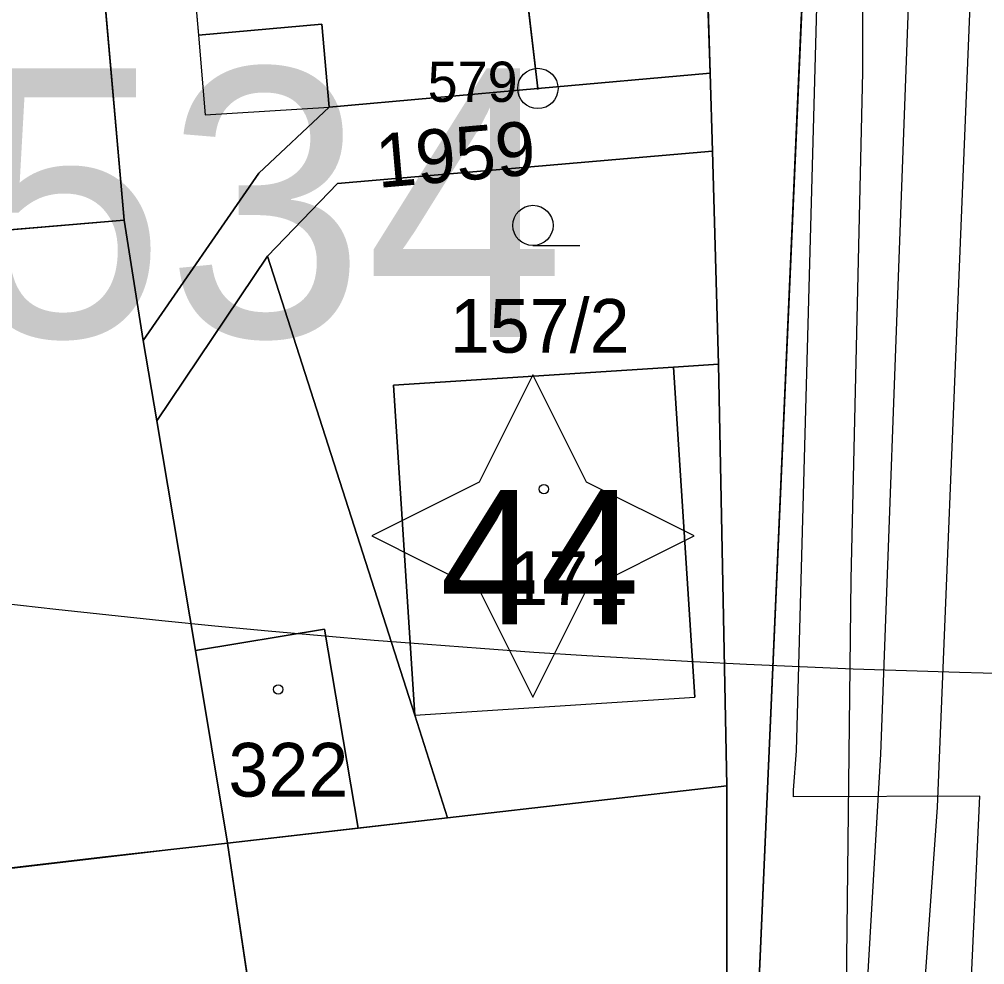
# Model space of a CAD drawing. Extents: x -706130 to -698555, y -971544 to -967260.
# Drawn here: x -704407.88 to -704371.94, y -970357.67 to -970322.46 of the extents above; entities that cross this region are included whole.
import ezdxf

# ---------------------------------------------------------------- set-up
doc = ezdxf.new("R2010")
doc.units = 0
for name, color, linetype in [('_Doplněk budov pro zastavěnost', 7, 'Continuous'), ('Architektonicky cenná stavba S', 7, 'Continuous'), ('BPEJ I-II trida ochrany S', 7, 'Continuous'), ('Docházková izochrona - BUS S', 7, 'Continuous'), ('Docházková izochrona - VLAK N', 7, 'Continuous'), ('Hranice intravilán', 7, 'Continuous'), ('Kanalizace_stoka bez rozlišení N', 7, 'Continuous'), ('KN_Budovy', 7, 'Continuous'), ('KN_Budovy_cisla_domovni', 7, 'Continuous'), ('KN_Hranice_parcel', 7, 'Continuous'), ('KN_Hranice_parcel_vnitrni_kresba', 7, 'Continuous'), ('KN_Parcelni cisla', 7, 'Continuous'), ('KN_Polygon parcely', 7, 'Continuous'), ('KN_POZEMKY_13_ZASTAVENA PLOCHA', 7, 'Continuous'), ('KN_POZEMKY_14_OSTATNI PLOCHA', 7, 'Continuous'), ('KN_POZEMKY_5_ZAHRADA', 7, 'Continuous'), ('KN_POZEMKY_7_TTP', 7, 'Continuous'), ('KN_VYUZITI_16_ostatni plocha_silnice', 7, 'Continuous'), ('KN_VYUZITI_17_ostatni plocha_ostatni komunikace', 7, 'Continuous'), ('KN_VYUZITI_20_ostatni plocha_sportoviste', 7, 'Continuous'), ('KN_Značky bodu BP', 7, 'Continuous'), ('KN_Značky budov', 7, 'Continuous'), ('KN_Značky kultur', 7, 'Continuous'), ('Komunikace III třídy osy S', 7, 'Continuous'), ('Nemovité kulturní památky popis', 7, 'Continuous'), ('Nemovité kulturní památky S', 7, 'Continuous'), ('Plochy doprava silniční - silnice III třídy S', 7, 'Continuous'), ('Plochy smíšené obytné venkovské S', 7, 'Continuous'), ('Plynovody STL S', 7, 'Continuous'), ('Regulační bloky zastavěné S', 7, 'Continuous'), ('Vodovodní řady - rozváděcí S', 7, 'Continuous')]:
    doc.layers.add(name, color=color, linetype=linetype)

msp = doc.modelspace()

# ---------------------------------------------------------------- linework, layer by layer
at = {"layer": '_Doplněk budov pro zastavěnost'}
for points in [[(-704396.34, -970325.73), (-704396.61, -970322.64), (-704401.2, -970323.05)], [(-704401.2, -970323.05), (-704400.954, -970326.017), (-704396.34, -970325.73)]]:
    msp.add_lwpolyline(points, dxfattribs=at)
at = {"layer": 'Architektonicky cenná stavba S'}
msp.add_lwpolyline([(-704388.754, -970335.704), (-704390.754, -970339.704), (-704394.754, -970341.704), (-704390.754, -970343.704), (-704388.754, -970347.704), (-704386.754, -970343.704), (-704382.754, -970341.704), (-704386.754, -970339.704)], close=True, dxfattribs=at)
at = {"layer": 'BPEJ I-II trida ochrany S'}
for p, q in [((-704403.97, -970329.94), (-704406.06, -970306.24)), ((-704382.07, -970327.37), (-704396.03, -970328.58)), ((-704381.84, -970335.31), (-704382.07, -970327.37)), ((-704396.03, -970328.58), (-704398.63, -970331.28)), ((-704403.26, -970334.42), (-704403.97, -970329.94)), ((-704398.63, -970331.28), (-704393.15, -970348.38)), ((-704402.76, -970337.42), (-704403.26, -970334.42)), ((-704383.52, -970335.42), (-704381.84, -970335.31)), ((-704393.94, -970336.09), (-704383.52, -970335.42)), ((-704393.15, -970348.38), (-704393.94, -970336.09)), ((-704401.32, -970345.97), (-704402.76, -970337.42)), ((-704400.12, -970353.14), (-704401.32, -970345.97)), ((-704395.76, -970382.45), (-704400.12, -970353.14))]:
    msp.add_line(p, q, dxfattribs=at)
at = {"layer": 'Docházková izochrona - BUS S'}
msp.add_arc((-704361.829, -969946.93), 400, 155.51821, 17.33949, dxfattribs=at)
at = {"layer": 'Docházková izochrona - VLAK N'}
msp.add_circle((-704165.451, -969778.767), 800, dxfattribs=at)
at = {"layer": 'Hranice intravilán'}
msp.add_lwpolyline([(-704381.54, -970369.54), (-704381.53, -970351.01), (-704391.93, -970352.2), (-704400.12, -970353.14), (-704436.16, -970357.37), (-704435.41, -970332.61), (-704434.49, -970307.92), (-704433.21, -970284.34), (-704432.24, -970260.61)], dxfattribs=at)
at = {"layer": 'Kanalizace_stoka bez rozlišení N'}
msp.add_lwpolyline([(-704315.708, -970108.899), (-704316.113, -970109.917), (-704324.867, -970134.026), (-704326.632, -970179.784), (-704337.75, -970213.085), (-704365.425, -970272.107), (-704371.374, -970294.506), (-704373.709, -970351.804), (-704376.113, -970385.719), (-704398.194, -970423.758)], dxfattribs=at)
at = {"layer": 'KN_Budovy'}
for points in [[(-704397.27, -970315.27), (-704401.85, -970315.68), (-704401.2, -970323.05), (-704396.61, -970322.64), (-704396.34, -970325.73), (-704388.57, -970325.04), (-704390.2, -970311.28), (-704397.56, -970312.03)], [(-704393.94, -970336.09), (-704393.15, -970348.38), (-704382.73, -970347.71), (-704383.52, -970335.42)], [(-704401.32, -970345.97), (-704400.12, -970353.14), (-704395.26, -970352.58), (-704396.51, -970345.18)]]:
    msp.add_lwpolyline(points, close=True, dxfattribs=at)
at = {"layer": 'KN_Hranice_parcel'}
for p, q in [((-704406.06, -970306.24), (-704403.97, -970329.94)), ((-704382.15, -970324.47), (-704382.57, -970312.21)), ((-704382.15, -970324.47), (-704382.07, -970327.37)), ((-704381.84, -970335.31), (-704382.07, -970327.37)), ((-704403.97, -970329.94), (-704435.41, -970332.61)), ((-704403.97, -970329.94), (-704403.26, -970334.42)), ((-704398.63, -970331.28), (-704402.76, -970337.42)), ((-704393.15, -970348.38), (-704398.63, -970331.28)), ((-704402.76, -970337.42), (-704403.26, -970334.42)), ((-704381.53, -970351.01), (-704381.84, -970335.31)), ((-704393.15, -970348.38), (-704391.93, -970352.2)), ((-704391.93, -970352.2), (-704381.53, -970351.01)), ((-704404.67, -970353.65), (-704400.12, -970353.14)), ((-704400.12, -970353.14), (-704395.76, -970382.45))]:
    msp.add_line(p, q, dxfattribs=at)
for points in [[(-704381.19, -970377.72), (-704380.01, -970350.84), (-704377.78, -970300.1), (-704377.45, -970297.32)], [(-704403.26, -970334.42), (-704398.96, -970328.19), (-704396.34, -970325.73), (-704388.57, -970325.04), (-704382.15, -970324.47)], [(-704382.07, -970327.37), (-704396.03, -970328.58), (-704398.63, -970331.28)], [(-704435.41, -970332.61), (-704436.16, -970357.37), (-704404.67, -970353.65)], [(-704381.84, -970335.31), (-704383.52, -970335.42), (-704393.94, -970336.09), (-704393.15, -970348.38)], [(-704402.76, -970337.42), (-704401.32, -970345.97), (-704400.12, -970353.14)], [(-704388.96, -970375.85), (-704387.88, -970369.26), (-704381.54, -970369.54), (-704381.53, -970351.01)], [(-704400.12, -970353.14), (-704395.26, -970352.58), (-704391.93, -970352.2)]]:
    msp.add_lwpolyline(points, dxfattribs=at)
at = {"layer": 'KN_Hranice_parcel_vnitrni_kresba'}
for p, q in [((-704390.2, -970311.28), (-704388.57, -970325.04)), ((-704401.85, -970315.68), (-704401.2, -970323.05)), ((-704401.2, -970323.05), (-704396.61, -970322.64)), ((-704396.61, -970322.64), (-704396.34, -970325.73)), ((-704383.52, -970335.42), (-704382.73, -970347.71)), ((-704401.32, -970345.97), (-704396.51, -970345.18)), ((-704396.51, -970345.18), (-704395.26, -970352.58)), ((-704393.15, -970348.38), (-704382.73, -970347.71))]:
    msp.add_line(p, q, dxfattribs=at)
at = {"layer": 'KN_Polygon parcely'}
msp.add_lwpolyline([(-704375.62, -970282.06), (-704376.41, -970288.62), (-704377.45, -970297.32), (-704377.78, -970300.1), (-704380.01, -970350.84), (-704381.19, -970377.72), (-704372.65, -970386.41), (-704371.76, -970369.3), (-704370.91, -970352.79), (-704370.59, -970346.53), (-704370.18, -970335.17), (-704369.52, -970316.88), (-704369.23, -970310.61), (-704368.75, -970300.09), (-704366.65, -970284.79), (-704361.08, -970269.38)], dxfattribs=at)
for points in [[(-704426.17, -970394.89), (-704421.76, -970392.36), (-704422.73, -970390.66), (-704416.04, -970386.82), (-704417.98, -970383.43), (-704409.73, -970378.7), (-704407.78, -970382.09), (-704403.26, -970379.5), (-704395.76, -970382.45), (-704400.12, -970353.14), (-704404.67, -970353.65), (-704436.16, -970357.37), (-704435.41, -970332.61), (-704434.49, -970307.92), (-704433.21, -970284.34), (-704437.36, -970284.18), (-704440.6, -970365.1), (-704426.93, -970393.32)], [(-704381.19, -970377.72), (-704380.01, -970350.84), (-704377.78, -970300.1), (-704377.45, -970297.32), (-704381.06, -970296.88), (-704381.15, -970298.64), (-704382.31, -970309.38), (-704382.57, -970312.21), (-704382.15, -970324.47), (-704382.07, -970327.37), (-704381.84, -970335.31), (-704381.53, -970351.01), (-704381.54, -970369.54), (-704387.88, -970369.26), (-704388.96, -970375.85)], [(-704406.09, -970304.49), (-704406.06, -970306.24), (-704403.97, -970329.94), (-704403.26, -970334.42), (-704398.96, -970328.19), (-704396.34, -970325.73), (-704388.57, -970325.04), (-704382.15, -970324.47), (-704382.57, -970312.21), (-704388.56, -970311.1), (-704389.75, -970308.75), (-704391.17, -970307.32), (-704394.63, -970305.83)], [(-704406.06, -970306.24), (-704434.49, -970307.92), (-704435.41, -970332.61), (-704403.97, -970329.94)], [(-704403.26, -970334.42), (-704402.76, -970337.42), (-704398.63, -970331.28), (-704396.03, -970328.58), (-704382.07, -970327.37), (-704382.15, -970324.47), (-704388.57, -970325.04), (-704396.34, -970325.73), (-704398.96, -970328.19)], [(-704381.84, -970335.31), (-704382.07, -970327.37), (-704396.03, -970328.58), (-704398.63, -970331.28), (-704393.15, -970348.38), (-704393.94, -970336.09), (-704383.52, -970335.42)], [(-704403.97, -970329.94), (-704435.41, -970332.61), (-704436.16, -970357.37), (-704404.67, -970353.65), (-704400.12, -970353.14), (-704401.32, -970345.97), (-704402.76, -970337.42), (-704403.26, -970334.42)], [(-704400.12, -970353.14), (-704395.26, -970352.58), (-704391.93, -970352.2), (-704393.15, -970348.38), (-704398.63, -970331.28), (-704402.76, -970337.42), (-704401.32, -970345.97)], [(-704393.94, -970336.09), (-704393.15, -970348.38), (-704391.93, -970352.2), (-704381.53, -970351.01), (-704381.84, -970335.31), (-704383.52, -970335.42)], [(-704387.88, -970369.26), (-704381.54, -970369.54), (-704381.53, -970351.01), (-704391.93, -970352.2), (-704395.26, -970352.58), (-704400.12, -970353.14), (-704395.76, -970382.45), (-704394.76, -970382.69), (-704392.9, -970374.9), (-704388.96, -970375.85)]]:
    msp.add_lwpolyline(points, close=True, dxfattribs=at)
at = {"layer": 'KN_POZEMKY_13_ZASTAVENA PLOCHA'}
for p, q in [((-704403.97, -970329.94), (-704406.06, -970306.24)), ((-704382.57, -970312.21), (-704382.15, -970324.47)), ((-704382.15, -970324.47), (-704388.57, -970325.04)), ((-704388.57, -970325.04), (-704396.34, -970325.73)), ((-704396.34, -970325.73), (-704398.96, -970328.19)), ((-704398.96, -970328.19), (-704403.26, -970334.42)), ((-704403.26, -970334.42), (-704403.97, -970329.94)), ((-704402.76, -970337.42), (-704398.63, -970331.28)), ((-704398.63, -970331.28), (-704393.15, -970348.38)), ((-704383.52, -970335.42), (-704381.84, -970335.31)), ((-704381.84, -970335.31), (-704381.53, -970351.01)), ((-704393.94, -970336.09), (-704383.52, -970335.42)), ((-704393.15, -970348.38), (-704393.94, -970336.09)), ((-704401.32, -970345.97), (-704402.76, -970337.42)), ((-704400.12, -970353.14), (-704401.32, -970345.97)), ((-704393.15, -970348.38), (-704391.93, -970352.2)), ((-704391.93, -970352.2), (-704393.15, -970348.38)), ((-704381.53, -970351.01), (-704391.93, -970352.2)), ((-704391.93, -970352.2), (-704395.26, -970352.58)), ((-704395.26, -970352.58), (-704400.12, -970353.14))]:
    msp.add_line(p, q, dxfattribs=at)
at = {"layer": 'KN_POZEMKY_14_OSTATNI PLOCHA'}
for p, q in [((-704380.01, -970350.84), (-704377.78, -970300.1)), ((-704377.78, -970300.1), (-704380.01, -970350.84)), ((-704382.15, -970324.47), (-704382.57, -970312.21)), ((-704388.57, -970325.04), (-704382.15, -970324.47)), ((-704382.15, -970324.47), (-704382.07, -970327.37)), ((-704382.07, -970327.37), (-704382.15, -970324.47)), ((-704396.34, -970325.73), (-704388.57, -970325.04)), ((-704398.96, -970328.19), (-704396.34, -970325.73)), ((-704382.07, -970327.37), (-704396.03, -970328.58)), ((-704381.84, -970335.31), (-704382.07, -970327.37)), ((-704403.26, -970334.42), (-704398.96, -970328.19)), ((-704396.03, -970328.58), (-704398.63, -970331.28)), ((-704398.63, -970331.28), (-704402.76, -970337.42)), ((-704402.76, -970337.42), (-704403.26, -970334.42)), ((-704381.53, -970351.01), (-704381.84, -970335.31)), ((-704391.93, -970352.2), (-704381.53, -970351.01)), ((-704381.53, -970351.01), (-704381.54, -970369.54)), ((-704381.54, -970369.54), (-704381.53, -970351.01)), ((-704381.19, -970377.72), (-704380.01, -970350.84)), ((-704380.01, -970350.84), (-704381.19, -970377.72)), ((-704395.26, -970352.58), (-704391.93, -970352.2)), ((-704400.12, -970353.14), (-704395.26, -970352.58)), ((-704395.76, -970382.45), (-704400.12, -970353.14))]:
    msp.add_line(p, q, dxfattribs=at)
at = {"layer": 'KN_POZEMKY_5_ZAHRADA'}
for p, q in [((-704406.06, -970306.24), (-704403.97, -970329.94)), ((-704396.03, -970328.58), (-704382.07, -970327.37)), ((-704382.07, -970327.37), (-704381.84, -970335.31)), ((-704398.63, -970331.28), (-704396.03, -970328.58)), ((-704403.97, -970329.94), (-704435.41, -970332.61)), ((-704393.15, -970348.38), (-704398.63, -970331.28)), ((-704381.84, -970335.31), (-704383.52, -970335.42)), ((-704383.52, -970335.42), (-704393.94, -970336.09)), ((-704393.94, -970336.09), (-704393.15, -970348.38))]:
    msp.add_line(p, q, dxfattribs=at)
at = {"layer": 'KN_POZEMKY_7_TTP'}
for p, q in [((-704435.41, -970332.61), (-704403.97, -970329.94)), ((-704403.97, -970329.94), (-704403.26, -970334.42)), ((-704403.26, -970334.42), (-704402.76, -970337.42)), ((-704402.76, -970337.42), (-704401.32, -970345.97)), ((-704401.32, -970345.97), (-704400.12, -970353.14)), ((-704404.67, -970353.65), (-704400.12, -970353.14)), ((-704400.12, -970353.14), (-704404.67, -970353.65)), ((-704400.12, -970353.14), (-704395.76, -970382.45)), ((-704436.16, -970357.37), (-704404.67, -970353.65)), ((-704404.67, -970353.65), (-704436.16, -970357.37))]:
    msp.add_line(p, q, dxfattribs=at)
at = {"layer": 'KN_VYUZITI_16_ostatni plocha_silnice'}
for p, q in [((-704380.01, -970350.84), (-704377.78, -970300.1)), ((-704381.19, -970377.72), (-704380.01, -970350.84))]:
    msp.add_line(p, q, dxfattribs=at)
at = {"layer": 'KN_VYUZITI_17_ostatni plocha_ostatni komunikace'}
for p, q in [((-704377.78, -970300.1), (-704380.01, -970350.84)), ((-704382.15, -970324.47), (-704382.57, -970312.21)), ((-704388.57, -970325.04), (-704382.15, -970324.47)), ((-704382.15, -970324.47), (-704382.07, -970327.37)), ((-704382.07, -970327.37), (-704382.15, -970324.47)), ((-704396.34, -970325.73), (-704388.57, -970325.04)), ((-704398.96, -970328.19), (-704396.34, -970325.73)), ((-704382.07, -970327.37), (-704396.03, -970328.58)), ((-704381.84, -970335.31), (-704382.07, -970327.37)), ((-704403.26, -970334.42), (-704398.96, -970328.19)), ((-704396.03, -970328.58), (-704398.63, -970331.28)), ((-704398.63, -970331.28), (-704402.76, -970337.42)), ((-704402.76, -970337.42), (-704403.26, -970334.42)), ((-704381.53, -970351.01), (-704381.84, -970335.31)), ((-704381.54, -970369.54), (-704381.53, -970351.01)), ((-704380.01, -970350.84), (-704381.19, -970377.72))]:
    msp.add_line(p, q, dxfattribs=at)
at = {"layer": 'KN_VYUZITI_20_ostatni plocha_sportoviste'}
for p, q in [((-704391.93, -970352.2), (-704381.53, -970351.01)), ((-704381.53, -970351.01), (-704381.54, -970369.54)), ((-704395.26, -970352.58), (-704391.93, -970352.2)), ((-704400.12, -970353.14), (-704395.26, -970352.58)), ((-704395.76, -970382.45), (-704400.12, -970353.14))]:
    msp.add_line(p, q, dxfattribs=at)
at = {"layer": 'KN_Značky bodu BP'}
for radius in [0.75, 0.03]:
    msp.add_circle((-704388.57, -970325.04), radius, dxfattribs=at)
at = {"layer": 'KN_Značky budov'}
for centre in [(-704388.347, -970339.959), (-704398.237, -970347.419)]:
    msp.add_circle(centre, 0.175, dxfattribs=at)
at = {"layer": 'KN_Značky kultur'}
msp.add_line((-704388.753, -970330.89), (-704387.003, -970330.89), dxfattribs=at)
msp.add_circle((-704388.753, -970330.14), 0.75, dxfattribs=at)
at = {"layer": 'Komunikace III třídy osy S'}
msp.add_lwpolyline([(-704330.93, -970188.51), (-704335.437, -970204.681), (-704336.48, -970208.22), (-704338.18, -970213.14), (-704340.791, -970218.395), (-704362.238, -970261.156), (-704368.668, -970276.027), (-704371.631, -970286.925), (-704374.154, -970304.881), (-704375.815, -970349.829), (-704377.52, -970379.09), (-704378.33, -970382.9), (-704379.81, -970387.16), (-704381.8, -970391.97), (-704383.72, -970396.25), (-704386.32, -970401.18), (-704392.36, -970410.73), (-704399.98, -970422.96)], dxfattribs=at)
at = {"layer": 'Nemovité kulturní památky S'}
msp.add_lwpolyline([(-704396.34, -970325.73), (-704388.57, -970325.04), (-704390.2, -970311.28), (-704397.56, -970312.03), (-704397.27, -970315.27), (-704401.85, -970315.68), (-704401.2, -970323.05), (-704396.61, -970322.64)], close=True, dxfattribs=at)
at = {"layer": 'Plochy doprava silniční - silnice III třídy S'}
for p, q in [((-704377.78, -970300.1), (-704380.01, -970350.84)), ((-704380.01, -970350.84), (-704381.19, -970377.72))]:
    msp.add_line(p, q, dxfattribs=at)
at = {"layer": 'Plochy smíšené obytné venkovské S'}
for p, q in [((-704380.01, -970350.84), (-704377.78, -970300.1)), ((-704381.19, -970377.72), (-704380.01, -970350.84))]:
    msp.add_line(p, q, dxfattribs=at)
at = {"layer": 'Plynovody STL S'}
msp.add_lwpolyline([(-704398.39, -970427.39), (-704384.69, -970404.86), (-704379.67, -970395.45), (-704375.66, -970385.74), (-704373.212, -970374.188), (-704372.471, -970359.213), (-704372.11, -970351.39), (-704379.05, -970351.42), (-704379.051, -970351.17), (-704378.94, -970349.71), (-704378.15, -970320.65), (-704377.62, -970309.79), (-704376.7, -970299.55), (-704375.786, -970291.541), (-704375.67, -970290.6), (-704375.535, -970290.001), (-704372.96, -970278.67)], dxfattribs=at)
at = {"layer": 'Regulační bloky zastavěné S'}
for p, q in [((-704380.01, -970350.84), (-704377.78, -970300.1)), ((-704377.78, -970300.1), (-704380.01, -970350.84)), ((-704381.19, -970377.72), (-704380.01, -970350.84)), ((-704380.01, -970350.84), (-704381.19, -970377.72))]:
    msp.add_line(p, q, dxfattribs=at)
at = {"layer": 'Vodovodní řady - rozváděcí S'}
msp.add_lwpolyline([(-704404.59, -970428.41), (-704404.4, -970428.06), (-704389.04, -970403.19), (-704382.84, -970391.74), (-704379.76, -970383.48), (-704377.93, -970375.71), (-704377.64, -970372.75), (-704377.15, -970365.02), (-704376.91, -970343.31), (-704376.47, -970324.43), (-704376.46, -970319.47), (-704375.71, -970303.28), (-704375.47, -970302.37), (-704374.67, -970295.69), (-704373.36, -970287.93), (-704370.399, -970278.264)], dxfattribs=at)

# ---------------------------------------------------------------- texts
at = {"layer": 'KN_Budovy_cisla_domovni'}
msp.add_text('44', height=5, dxfattribs=at).set_placement((-704392.218, -970344.989))
at = {"layer": 'KN_Parcelni cisla'}
msp.add_text('1959', height=2, rotation=5, dxfattribs=at).set_placement((-704394.515, -970328.746))
for s, p in [('157/2', (-704391.85, -970334.88)), ('171', (-704389.67, -970344.27)), ('322', (-704400.09, -970351.41))]:
    msp.add_text(s, height=2, dxfattribs=at).set_placement(p)
at = {"layer": 'KN_Značky bodu BP'}
msp.add_text('579', height=1.5, dxfattribs=at).set_placement((-704392.673, -970325.54))
at = {"layer": 'Nemovité kulturní památky popis'}
msp.add_text('100534', height=10, dxfattribs=at).set_placement((-704432.176, -970334.289))

doc.saveas('drawing.dxf')
